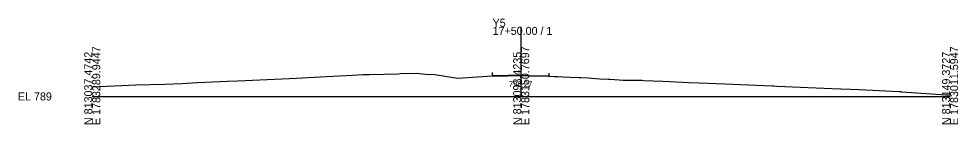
# Model space of a CAD drawing. Extents: x -26 to 1603, y -10 to 6526.
# Drawn here: x 1274.3 to 1602.8, y 4490.3 to 4527.1 of the extents above; entities that cross this region are included whole.
import ezdxf

# ---------------------------------------------------------------- set-up
doc = ezdxf.new("R2010")
doc.units = 0
for name, color, linetype in [('Exist Cross Section Cell', 7, 'Continuous'), ('Exist XS Center Line Elevation Label', 7, 'Continuous'), ('Exist XS Ground Line', 7, 'Continuous'), ('Prop XS EOT Tick Mark', 7, 'Continuous'), ('Prop XS Finish Grade Pavement', 7, 'Continuous')]:
    doc.layers.add(name, color=color, linetype=linetype)

msp = doc.modelspace()

# ---------------------------------------------------------------- linework, layer by layer
at = {"layer": 'Exist Cross Section Cell'}
for p, q in [((1450, 4500), (1450, 4524.31)), ((1300, 4500), (1450, 4500)), ((1450, 4500), (1600, 4500))]:
    msp.add_line(p, q, dxfattribs=at)
at = {"layer": 'Exist XS Ground Line'}
for p, q in [((1390.97, 4507.46), (1394.57, 4507.63)), ((1394.57, 4507.63), (1395.67, 4507.67)), ((1395.67, 4507.67), (1396.94, 4507.7)), ((1396.94, 4507.7), (1407.18, 4507.93)), ((1407.18, 4507.93), (1407.74, 4507.99)), ((1407.74, 4507.99), (1413.46, 4508.1)), ((1413.46, 4508.1), (1416.42, 4507.81)), ((1416.42, 4507.81), (1419.86, 4507.68)), ((1419.86, 4507.68), (1427.68, 4506.39)), ((1315.22, 4504.11), (1325.33, 4504.24)), ((1325.33, 4504.24), (1331.29, 4504.56)), ((1331.29, 4504.56), (1336.86, 4504.88)), ((1336.86, 4504.88), (1347.32, 4505.31)), ((1347.32, 4505.31), (1350.88, 4505.48)), ((1350.88, 4505.48), (1363.73, 4506.02)), ((1363.73, 4506.02), (1371.46, 4506.37)), ((1371.46, 4506.37), (1379.67, 4506.9)), ((1379.67, 4506.9), (1390.97, 4507.46)), ((1427.68, 4506.39), (1440.02, 4507.21)), ((1440.02, 4507.21), (1445.48, 4507.25)), ((1445.48, 4507.25), (1449.92, 4507.27)), ((1449.92, 4507.27), (1452.92, 4507.2)), ((1452.92, 4507.2), (1459.6, 4507.06)), ((1459.6, 4507.06), (1461.39, 4506.97)), ((1461.39, 4506.97), (1462.77, 4506.93)), ((1462.77, 4506.93), (1464.55, 4506.87)), ((1464.55, 4506.87), (1466.98, 4506.78)), ((1466.98, 4506.78), (1470.29, 4506.65)), ((1470.29, 4506.65), (1470.96, 4506.62)), ((1470.96, 4506.62), (1473.42, 4506.47)), ((1473.42, 4506.47), (1474.63, 4506.39)), ((1474.63, 4506.39), (1476, 4506.31)), ((1476, 4506.31), (1477.55, 4506.15)), ((1477.55, 4506.15), (1480.56, 4506.03)), ((1480.56, 4506.03), (1480.95, 4506)), ((1480.95, 4506), (1484.23, 4505.77)), ((1484.23, 4505.77), (1485.52, 4505.67)), ((1485.52, 4505.67), (1486.44, 4505.67)), ((1486.44, 4505.67), (1492.24, 4505.64)), ((1492.24, 4505.64), (1492.77, 4505.61)), ((1492.77, 4505.61), (1499.5, 4505.39)), ((1499.5, 4505.39), (1506.47, 4504.94)), ((1506.47, 4504.94), (1508.46, 4504.86)), ((1508.46, 4504.86), (1512.22, 4504.71)), ((1512.22, 4504.71), (1521.24, 4504.38)), ((1521.24, 4504.38), (1537.82, 4503.72)), ((1300, 4503.34), (1302.28, 4503.43)), ((1302.28, 4503.43), (1310.3, 4503.87)), ((1310.3, 4503.87), (1315.22, 4504.11)), ((1537.82, 4503.72), (1538.33, 4503.69)), ((1538.33, 4503.69), (1539.4, 4503.64)), ((1539.4, 4503.64), (1558.64, 4502.81)), ((1558.64, 4502.81), (1568.25, 4502.4)), ((1568.25, 4502.4), (1582.18, 4501.7)), ((1582.18, 4501.7), (1582.74, 4501.67)), ((1582.74, 4501.67), (1583.05, 4501.64)), ((1583.05, 4501.64), (1586.48, 4501.39)), ((1586.48, 4501.39), (1596.73, 4500.65)), ((1596.73, 4500.65), (1598.44, 4500.52)), ((1598.44, 4500.52), (1600, 4500.51))]:
    msp.add_line(p, q, dxfattribs=at)
at = {"layer": 'Prop XS EOT Tick Mark'}
for p, q in [((1440.02, 4507.34), (1440.02, 4508.34)), ((1459.84, 4507.17), (1459.84, 4508.17))]:
    msp.add_line(p, q, dxfattribs=at)
at = {"layer": 'Prop XS Finish Grade Pavement'}
for p, q in [((1440.02, 4507.34), (1445.48, 4507.38)), ((1445.48, 4507.38), (1449.92, 4507.39)), ((1449.92, 4507.39), (1452.92, 4507.32)), ((1452.92, 4507.32), (1459.6, 4507.18)), ((1459.6, 4507.18), (1459.84, 4507.17))]:
    msp.add_line(p, q, dxfattribs=at)

# ---------------------------------------------------------------- texts
at = {"layer": 'Exist Cross Section Cell'}
for s, p in [('Y5', (1440, 4524.31)), ('17+50.00 / 1', (1440, 4521.51)), ('EL 789', (1274, 4498.6))]:
    msp.add_text(s, height=2.8, dxfattribs=at).set_placement(p)
for s, p in [('N 813037.4742', (1300, 4490)), ('E 1783289.9447', (1302.8, 4490)), ('N 813093.4235', (1450, 4490)), ('E 1783150.7697', (1452.8, 4490)), ('N 813149.3727', (1600, 4490)), ('E 1783011.5947', (1602.8, 4490))]:
    msp.add_text(s, height=2.8, rotation=90, dxfattribs=at).set_placement(p)
at = {"layer": 'Exist XS Center Line Elevation Label'}
msp.add_text('796.27', height=2, dxfattribs=at).set_placement((1445.7, 4503.27))

doc.saveas('drawing.dxf')
